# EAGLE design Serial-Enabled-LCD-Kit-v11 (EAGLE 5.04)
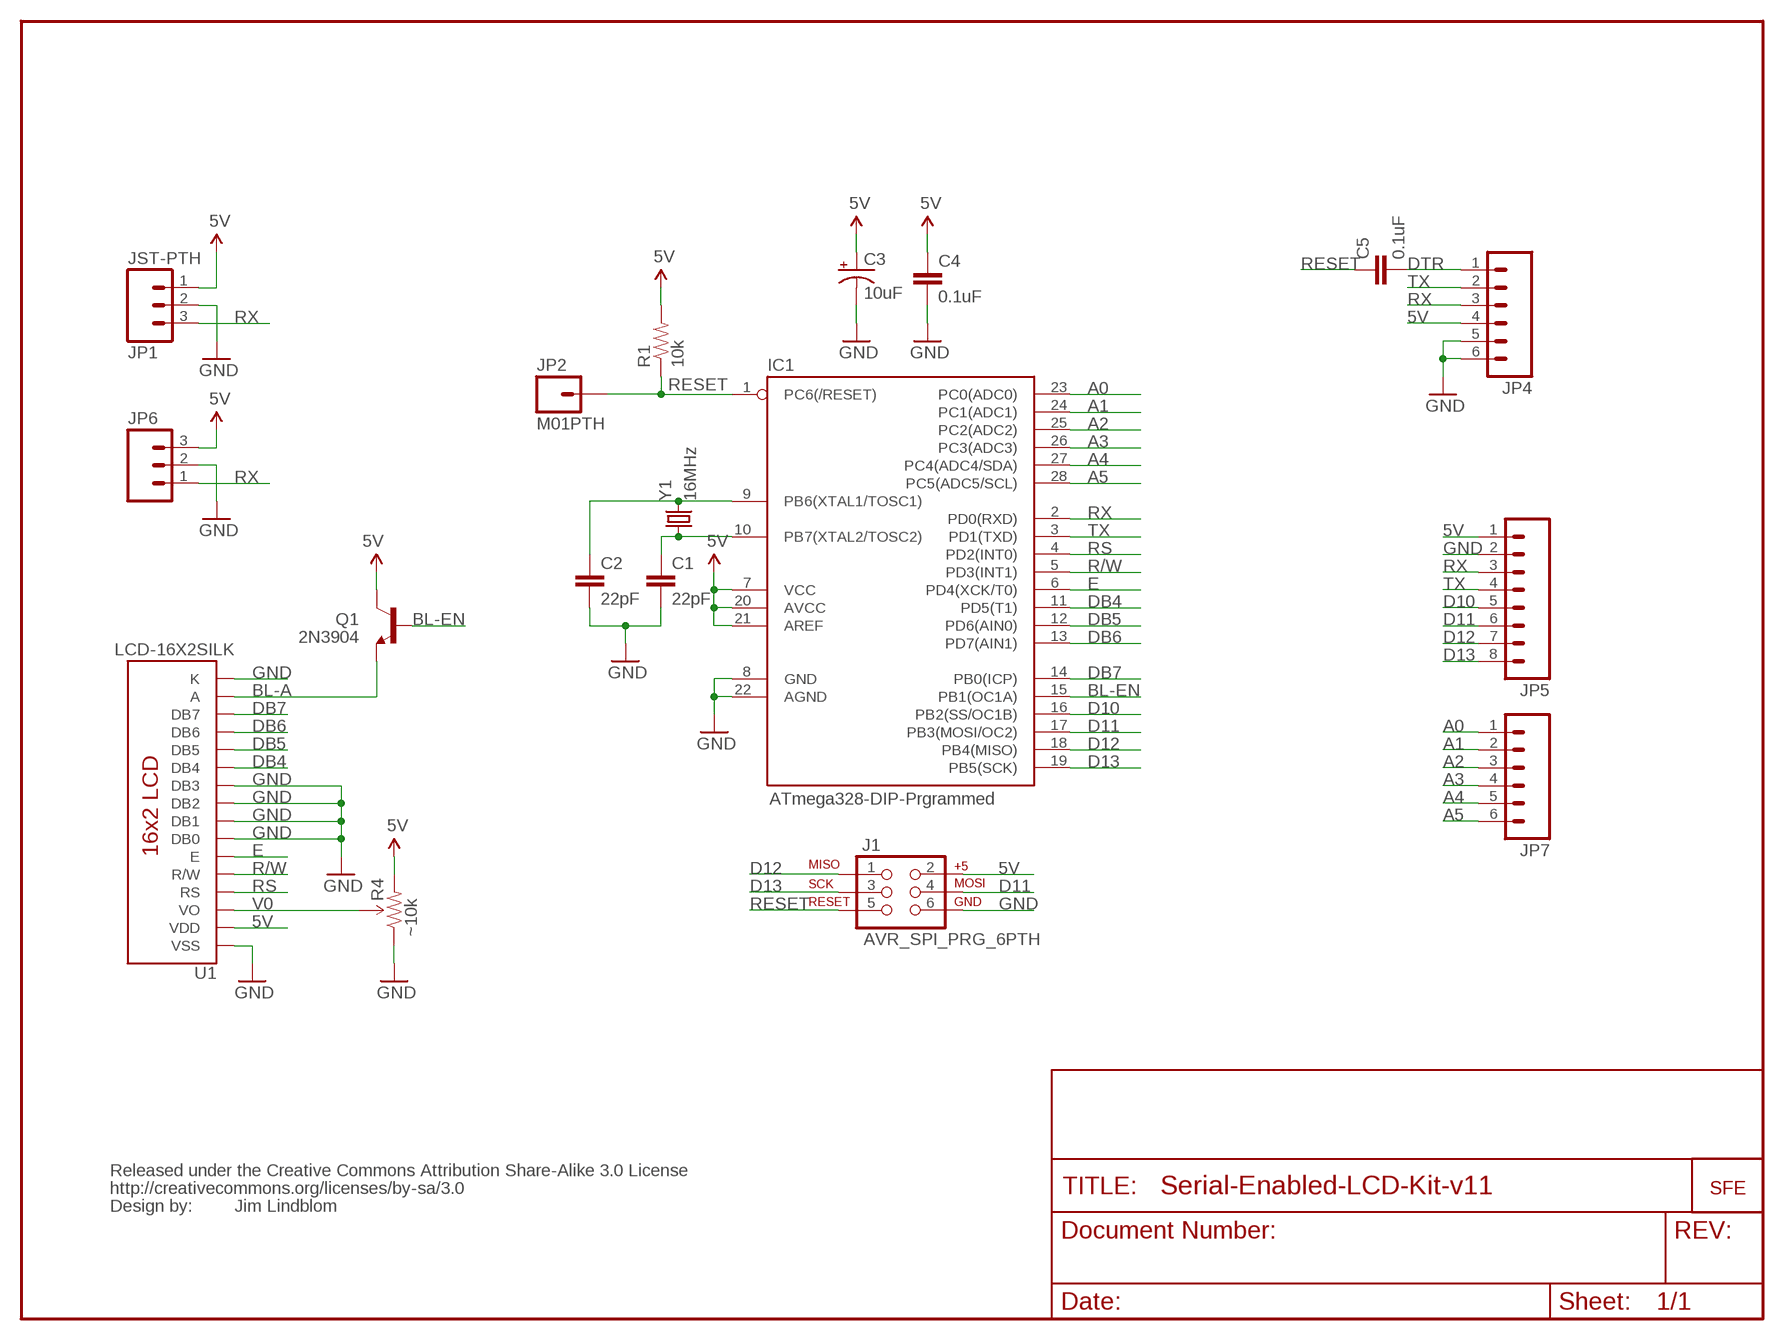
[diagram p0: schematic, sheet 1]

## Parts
C1  22pF  CAPPTH2  [CAP-PTH-SMALL2]
C2  22pF  CAPPTH2  [CAP-PTH-SMALL2]
C3  10uF  CAP_POLPTH2  [CPOL-RADIAL-10UF-25V]
C4  0.1uF  CAPPTH2  [CAP-PTH-SMALL2]
C5  0.1uF  CAPPTH2  [CAP-PTH-SMALL2]
IC1  ATmega328-DIP-Prgrammed  AVR-MEGA8-PPTH  [DIL28-3]
J1  AVR_SPI_PRG_6PTH  [2X3]
JP1  JST-PTH  M03JST-PTH  [JST-3-PTH]
JP2  M01PTH  [1X01]
JP3  LOGO-SFENEW  [SFE-NEW-WEBLOGO]
JP4  M06SIP  [1X06]
JP5  M08  [1X08]
JP6  M03PTH  [1X03]
JP7  M06SIP  [1X06]
Q1  2N3904  TRANSISTOR_NPNTO92  [TO-92]
R1  10k  RESISTORAXIAL-0.3  [AXIAL-0.3]
R4  ~10k  TRIMPOT-PTH-KNOB  [3386U]
U1  LCD-16X2SILK  [LCD-16X2]
U$4  CREATIVE_COMMONS  [CREATIVE_COMMONS]
Y1  16MHz  CRYSTALHC49US  [HC49US]

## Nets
5V: C3.1(+) C4.1 IC1.7(VCC) IC1.20(AVCC) IC1.21(AREF) J1.2 JP1.1 JP4.4 JP5.1 JP6.3 Q1.3(C) R1.P$2 R4.3(CW) U1.2(VDD)
A0: IC1.23(PC0(ADC0)) JP7.1
A1: IC1.24(PC1(ADC1)) JP7.2
A2: IC1.25(PC2(ADC2)) JP7.3
A3: IC1.26(PC3(ADC3)) JP7.4
A4: IC1.27(PC4(ADC4/SDA)) JP7.5
A5: IC1.28(PC5(ADC5/SCL)) JP7.6
BL-A: Q1.1(E) U1.15(A)
BL-EN: IC1.15(PB1(OC1A)) Q1.2(B)
D10: IC1.16(PB2(SS/OC1B)) JP5.5
D11: IC1.17(PB3(MOSI/OC2)) J1.4 JP5.6
D12: IC1.18(PB4(MISO)) J1.1 JP5.7
D13: IC1.19(PB5(SCK)) J1.3 JP5.8
DB4: IC1.11(PD5(T1)) U1.11(DB4)
DB5: IC1.12(PD6(AIN0)) U1.12(DB5)
DB6: IC1.13(PD7(AIN1)) U1.13(DB6)
DB7: IC1.14(PB0(ICP)) U1.14(DB7)
DTR: C5.2 JP4.1
E: IC1.6(PD4(XCK/T0)) U1.6(E)
GND: C1.2 C2.2 C3.2(-) C4.2 IC1.8(GND) IC1.22(AGND) J1.6 JP1.2 JP4.5 JP4.6 JP5.2 JP6.2 R4.1(CCW) U1.1(VSS) U1.7(DB0) U1.8(DB1) U1.9(DB2) U1.10(DB3) U1.16(K)
R/W: IC1.5(PD3(INT1)) U1.5(R/W)
RESET: C5.1 IC1.1(PC6(/RESET)) J1.5 JP2.1 R1.P$1
RS: IC1.4(PD2(INT0)) U1.4(RS)
RX: IC1.2(PD0(RXD)) JP1.3 JP4.3 JP5.3 JP6.1
TX: IC1.3(PD1(TXD)) JP4.2 JP5.4
V0: R4.2(WIPER) U1.3(VO)
XTAL1: C2.1 IC1.9(PB6(XTAL1/TOSC1)) Y1.2
XTAL2: C1.1 IC1.10(PB7(XTAL2/TOSC2)) Y1.1

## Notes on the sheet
- Jim Lindblom

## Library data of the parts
C1 C2 C4 C5 = SparkFun:CAP: Capacitor
C3 = SparkFun:CAP_POL: Capacitor Polarized
IC1 = SparkFun:AVR-MEGA8-P: MICROCONTROLLER 8 Kbytes FLASH 1 kbytes SRAM 512 bytes EEPROM USART 4-channel 10 bit ADC 2-channel 8 bit ADC
J1 = SparkFun:AVR_SPI_PRG_6: AVR ISP 6 Pin This is the reduced ISP connector for AVR programming. Common on Arduino. This footprint will take up less PCB space and can be used with a 10-pin to 6-pin adapter such as SKU: BOB-08508
JP1 JP6 = SparkFun:M03: Header 3 Standard 3-pin 0.1" header. Use with straight break away headers (SKU : PRT-00116), right angle break away headers (PRT-00553), swiss pins (PRT-00743), machine pins (PRT-00117), and female headers (PRT-00115). Molex polarized connector foot print use with SKU : PRT-08232 with associated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
JP2 = SparkFun:M01: Header 1
JP3 = SparkFun:LOGO-SFE: Spark Fun Electronics PCB Logo
JP4 JP7 = SparkFun:M06: Header 6 Standard 6-pin 0.1" header. Use with straight break away headers (SKU : PRT-00116), right angle break away headers (PRT-00553), swiss pins (PRT-00743), machine pins (PRT-00117), and female headers (PRT-00115). Molex polarized connector foot print use with SKU : PRT-08094 with associated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
JP5 = SparkFun:M08: Header 8 Standard 8-pin 0.1" header. Use with straight break away headers (SKU : PRT-00116), right angle break away headers (PRT-00553), swiss pins (PRT-00743), machine pins (PRT-00117), and female headers (PRT-00115).
Q1 = SparkFun:TRANSISTOR_NPN: Transistor NPN BJT configuration in SOT23 package. MMBT2222 is the common NPN we use. Double check BCE configuration again layout.
R1 = SparkFun:RESISTOR: Resistor
R4 = SparkFun:TRIMPOT
U1 = SparkFun:LCD-16X2
U$4 = SparkFun:CREATIVE_COMMONS
Y1 = SparkFun:CRYSTAL: Crystals

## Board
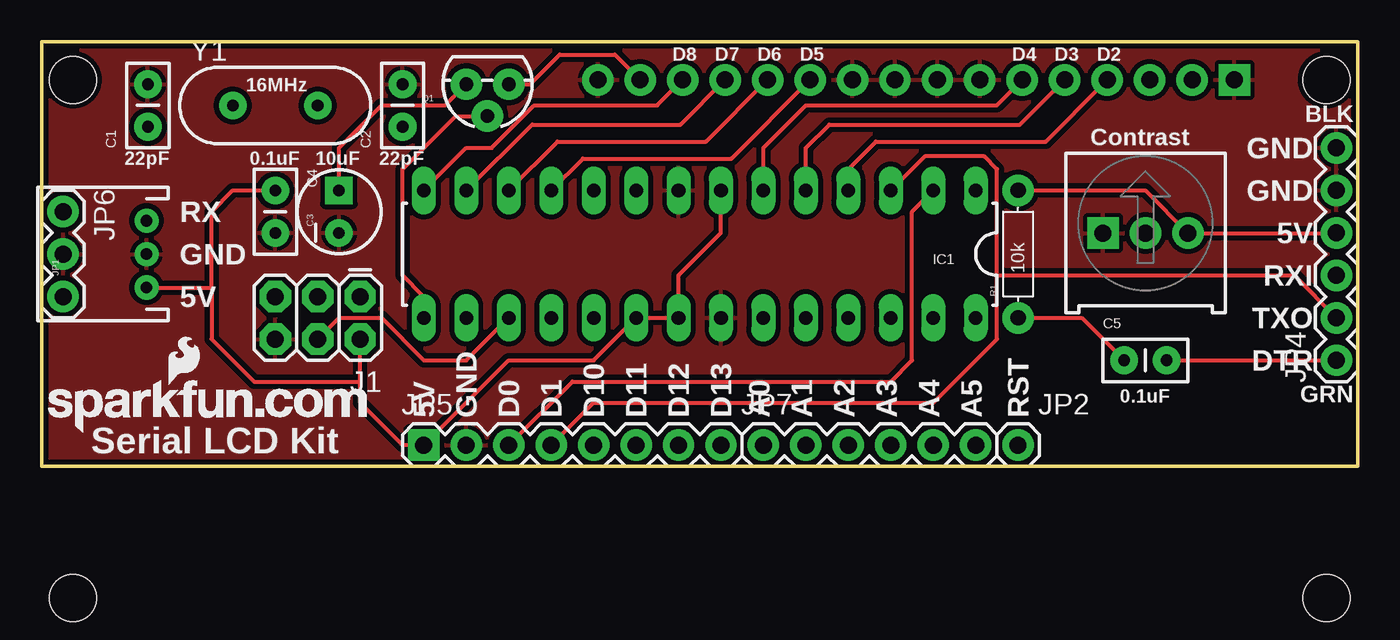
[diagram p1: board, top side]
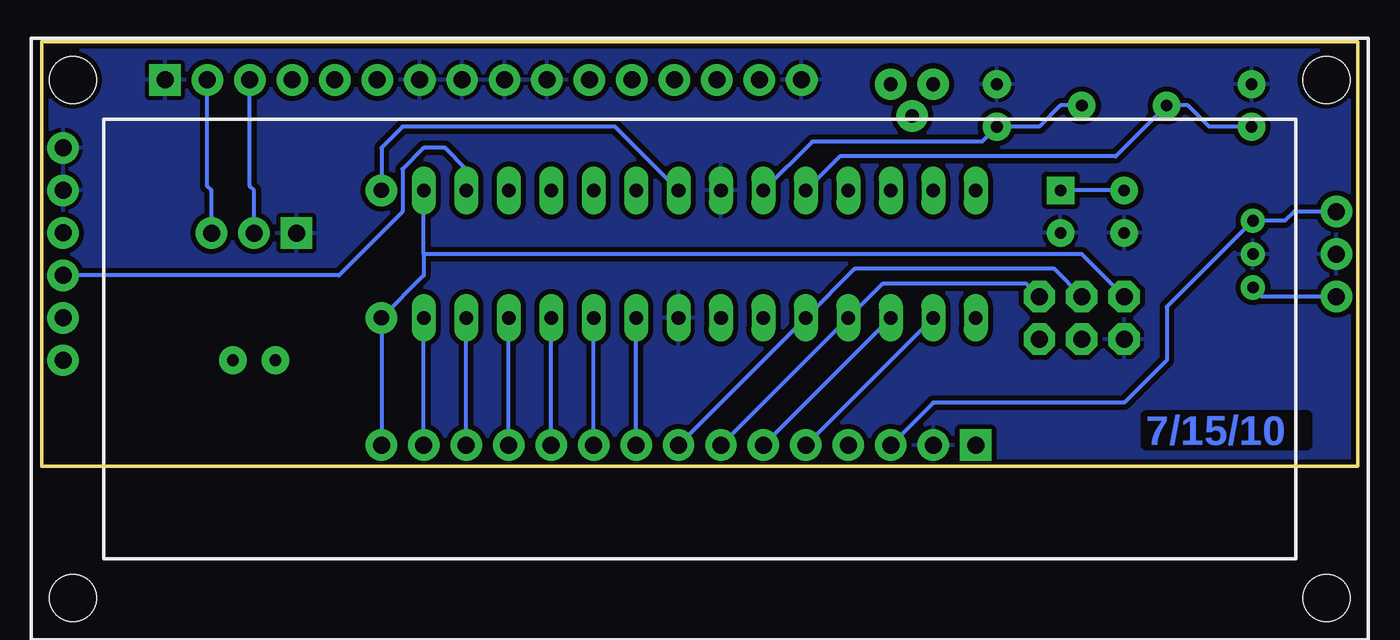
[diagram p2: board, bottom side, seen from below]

Size 78.74 x 25.4 mm. Coordinates in mm from the lower left corner, seen from the top.
Outline: 78.74,0 78.74,25.4 0,25.4 0,0 78.74,0
Copper layers (1*16): Top 0.035mm / dielectric 1.5mm / Bottom 0.035mm
Design rules "SparkFun": minimum track width 8mil, minimum drill 20mil, track to track 8mil, track to pad 8mil, pad to pad 8mil, via to via 8mil, smd to smd 8mil, copper to edge 8mil, drill to drill 8mil, minimum pad ring 12mil, minimum via ring 10mil, stop-mask expansion 4mil, vias tented up to drill 20mil, thermal gap 10mil

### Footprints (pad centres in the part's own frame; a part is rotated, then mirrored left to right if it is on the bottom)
CAP-PTH-SMALL2 = drill 0.7 pad 1.651 round: 1 0,0; 2 2.54,0
CPOL-RADIAL-10UF-25V = drill 0.7 pad 1.651 square: 1 1.27,0 | drill 0.7 pad 1.651 round: 2 -1.27,0
DIL28-3 = drill 0.813 long: 1 -16.51,-3.81; 2 -13.97,-3.81; 3 -11.43,-3.81; 4 -8.89,-3.81; 5 -6.35,-3.81; 6 -3.81,-3.81; 7 -1.27,-3.81; 8 1.27,-3.81; 9 3.81,-3.81; 10 6.35,-3.81; 11 8.89,-3.81; 12 11.43,-3.81; 13 13.97,-3.81; 14 16.51,-3.81; 15 16.51,3.81; 16 13.97,3.81; 17 11.43,3.81; 18 8.89,3.81; 19 6.35,3.81; 20 3.81,3.81; 21 1.27,3.81; 22 -1.27,3.81; 23 -3.81,3.81; 24 -6.35,3.81; 25 -8.89,3.81; 26 -11.43,3.81; 27 -13.97,3.81; 28 -16.51,3.81
2X3 = drill 1.016 pad 1.88 octagon: 1 0,0; 2 0,2.54; 3 2.54,0; 4 2.54,2.54; 5 5.08,0; 6 5.08,2.54
JST-3-PTH = drill 0.7 pad 1.448 round: 1 -2,-5; 2 0,-5; 3 2,-5
1X01 = drill 1.016 pad 1.88 round: 1 0,0
1X06 = drill 1.016 pad 1.88 round: 1 0,0; 2 2.54,0; 3 5.08,0; 4 7.62,0; 5 10.16,0; 6 12.7,0
1X08 = drill 1.016 pad 1.88 square: 1 0,0 | drill 1.016 pad 1.88 round: 2 2.54,0; 3 5.08,0; 4 7.62,0; 5 10.16,0; 6 12.7,0; 7 15.24,0; 8 17.78,0
1X03 = drill 1.016 pad 1.88 round: 1 0,0; 2 2.54,0; 3 5.08,0
TO-92 = drill 0.813 pad 1.88 round: 1 -1.27,0; 2 0,1.905; 3 1.27,0
AXIAL-0.3 = drill 0.9 pad 1.88 round: P$1 -3.81,0; P$2 3.81,0
3386U = drill 1.016 pad 1.88 square: 1 -2.54,-0.015 | drill 1.016 pad 1.88 round: 2 0,-0.015; 3 2.54,-0.015
LCD-16X2 = drill 1.016 pad 1.88 square: 1 -32,15.5 | drill 1.016 pad 1.88 round: 2 -29.46,15.5; 3 -26.92,15.5; 4 -24.38,15.5; 5 -21.84,15.5; 6 -19.3,15.5; 7 -16.76,15.5; 8 -14.22,15.5; 9 -11.68,15.5; 10 -9.14,15.5; 11 -6.6,15.5; 12 -4.06,15.5; 13 -1.52,15.5; 14 1.02,15.5; 15 3.56,15.5; 16 6.1,15.5 | hole 2.8: -37.5,15.5; -37.5,-15.5; 37.5,15.5; 37.5,-15.5
HC49US = drill 0.7 pad 1.651 round: 1 -2.54,0; 2 2.54,0

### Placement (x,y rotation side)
C1  6.35,20.32 90 top
C2  21.59,20.32 90 top
C3  17.78,15.24 90 top
C4  13.97,16.51 270 top
C5  64.77,6.35 0 top
IC1  39.37,12.7 180 top
J1  19.05,10.16 180 top
JP1  1.27,12.7 90 top
JP2  58.42,1.27 0 top
JP3  0.38,2.03 0 top
JP4  77.47,6.35 90 top
JP5  22.86,1.27 0 top
JP6  1.27,15.24 270 top
JP7  43.18,1.27 0 top
Q1  26.67,22.86 180 top
R1  58.42,12.7 90 top
R4  66.04,13.97 0 top
U1  39.37,7.62 0 bottom
U$4  not placed on the board
Y1  13.97,21.59 0 top

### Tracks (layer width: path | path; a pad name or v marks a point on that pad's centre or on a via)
5V
  Top 0.254: Q1.3 24.13,21.59 20.32,21.59 17.78,19.05 C3.1 | IC1.7 40.64,13.97 38.1,11.43 IC1.21 IC1.20 33.02,6.35 27.94,6.35 JP5.1 21.59,1.27 19.05,3.81 19.05,5.08 | R1.P$2 66.03,16.51 R4.3 77.45,13.96 JP4.4 | C4.1 11.43,16.51 10.16,15.24 10.16,10.67 | 10.16,10.67 10.16,7.62 12.7,5.08 19.05,5.08 | JP1.1 10.13,10.7 10.16,10.67 | 19.05,5.08 J1.2
  Bottom 0.254: JP6.3 5.73,10.16 JP1.1 | C4.1 C3.1 | IC1.7 44.45,20.32 57.15,20.32 58.42,19.05 R1.P$2 | U1.2 68.83,16.76 68.58,16.51 R4.3
A0
  Bottom 0.254: JP7.1 IC1.23
A1
  Bottom 0.254: JP7.2 IC1.24
A2
  Bottom 0.254: JP7.3 IC1.25
A3
  Bottom 0.254: JP7.4 IC1.26
A4
  Bottom 0.254: JP7.5 IC1.27
A5
  Bottom 0.254: JP7.6 IC1.28
BL-A
  Top 0.254: Q1.1 29.21,22.86 30.99,24.64 34.29,24.64 U1.15
BL-EN
  Top 0.254: Q1.2 24.77,20.95 21.59,17.78 21.59,11.43 22.86,10.16 IC1.15
D10
  Bottom 0.254: JP5.5 IC1.16
D11
  Top 0.254: J1.4 17.78,8.89 20.32,8.89 22.86,6.35 25.4,6.35 IC1.17
  Bottom 0.254: IC1.17 JP5.6
D12
  Bottom 0.254: JP5.7 IC1.18 28.45,10.92 19.81,10.92 J1.1
D13
  Bottom 0.254: JP5.8 IC1.19 30.1,11.81 18.16,11.81 J1.3
DB4
  Top 0.254: U1.11 41.27,18.41 32.38,18.41 IC1.11
DB5
  Top 0.254: U1.12 39.74,19.43 30.86,19.43 IC1.12
DB6
  Top 0.254: U1.13 38.22,20.45 29.34,20.45 IC1.13
DB7
  Top 0.254: IC1.14 25.4,19.05 26.92,19.05 29.46,21.59 36.82,21.59 U1.14
DTR
  Top 0.254: C5.2 JP4.1
E
  Top 0.254: U1.6 57.14,21.59 45.72,21.59 43.18,19.05 IC1.6
GND
  pour Bottom (isolate 0.305): 0,25.4 0,0 78.74,0 78.74,25.4
  pour Top (isolate 0.305): 0,25.4 0,0 78.74,0 78.74,25.4
R/W
  Top 0.254: IC1.5 45.72,19.05 47.12,20.45 58.54,20.45 U1.5
RESET
  Top 0.254: R1.P$1 62.23,8.89 C5.1
  Bottom 0.254: J1.5 16.51,12.7 55.88,12.7 | JP2.1 R1.P$1 55.88,11.43 55.88,12.7 | 55.88,12.7 IC1.1
RS
  Top 0.254: IC1.4 48.26,17.78 49.91,19.43 60.07,19.43 63.5,22.86 63.5,22.87 U1.4
RX
  Top 0.254: IC1.2 52.07,15.24 52.07,6.35 50.8,5.08 31.75,5.08 JP5.3
  Bottom 0.254: IC1.2 53.34,17.78 54.61,19.05 55.88,19.05 57.15,17.78 57.15,15.24 60.96,11.43 JP4.3 | JP6.1 3.81,15.24 4.35,14.7 JP1.3 11.43,9.54 11.43,6.35 13.97,3.81 25.4,3.81 JP5.3
TX
  Top 0.254: JP5.4 33.02,3.81 53.34,3.81 57.15,7.62 57.15,11.43 | 57.15,11.43 57.15,17.78 56.39,18.54 52.83,18.54 IC1.3 | JP4.2 74.93,11.43 57.15,11.43
V0
  Bottom 0.254: R4.2 66.04,16.51 66.29,16.76 U1.3
XTAL1
  Bottom 0.254: Y1.2 17.78,21.59 19.05,20.32 C2.1 22.48,19.43 32.64,19.43 IC1.9
XTAL2
  Bottom 0.254: C1.1 8.89,20.32 10.16,21.59 Y1.1 14.48,18.54 30.99,18.54 IC1.10

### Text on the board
Bottom: 7/15/10
tPlace: D8 | D7 | D6 | D5 | D4 | D3 | D2 | 16MHz | BLK | GND | Contrast | 22pF | 0.1uF | 10uF | 22pF | GND | RX | 5V | GND | RXI | 5V | TXO | DTR | GRN | 0.1uF | 5V | GND | D0 | D1 | D10 | D11 | D12 | D13 | A0 | A1 | A2 | A3 | A4 | A5 | RST | Serial LCD Kit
